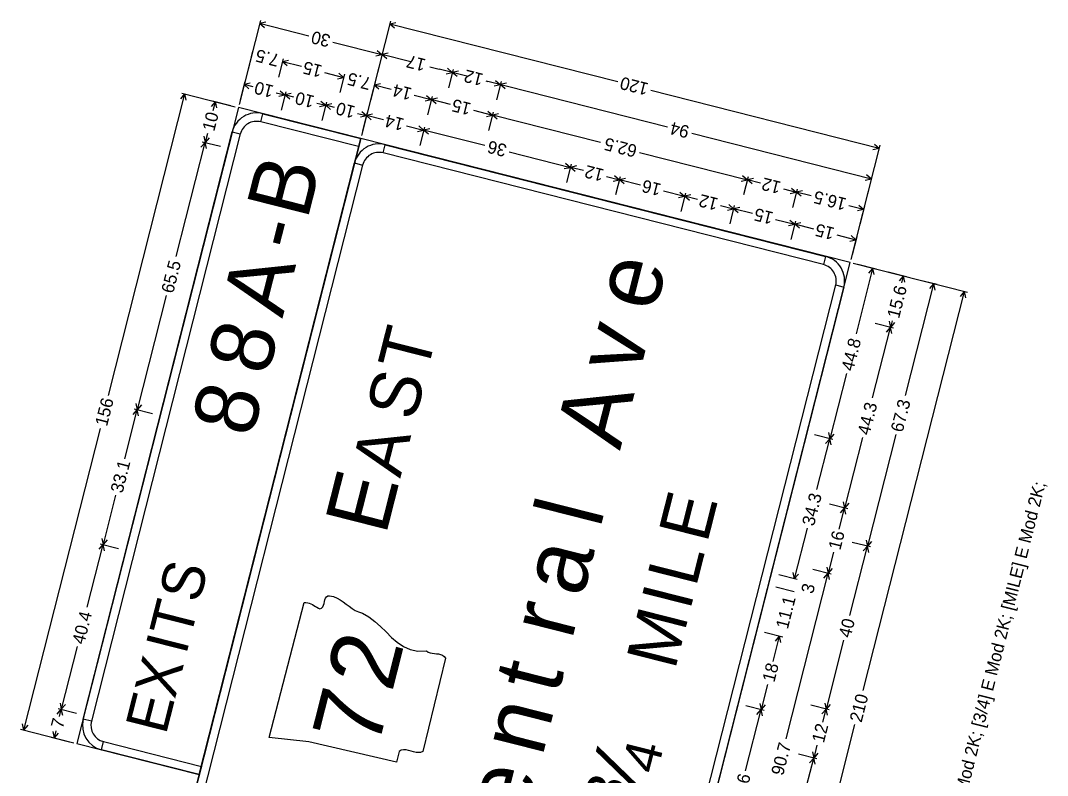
# Model space of a CAD drawing. Extents: x 670006 to 670131, y 737844 to 738002.
# Drawn here: x 670006.01 to 670044.77, y 737866.83 to 737895.33 of the extents above; entities that cross this region are included whole.
import ezdxf

# ---------------------------------------------------------------- set-up
doc = ezdxf.new("R2010")
doc.units = 0
doc.layers.add('R_SIGN', color=7, linetype='Continuous')

msp = doc.modelspace()

# ---------------------------------------------------------------- linework, layer by layer
at = {"layer": 'R_SIGN'}
for p, q in [((670015.059, 737895.329), (670014.256, 737892.162)), ((670015.262, 737895.264), (670015.03, 737895.213)), ((670016.884, 737894.743), (670015.03, 737895.213)), ((670015.21, 737895.058), (670015.03, 737895.213)), ((670019.97, 737895.309), (670018.874, 737890.99)), ((670020.173, 737895.244), (670019.941, 737895.194)), ((670028.558, 737893.008), (670019.941, 737895.194)), ((670020.12, 737895.038), (670019.941, 737895.194)), ((670017.794, 737894.512), (670019.648, 737894.042)), ((670014.767, 737894.177), (670014.592, 737893.486)), ((670019.678, 737894.157), (670018.874, 737890.99)), ((670019.416, 737893.991), (670019.648, 737894.042)), ((670019.469, 737894.197), (670019.648, 737894.042)), ((670019.678, 737894.157), (670019.502, 737893.466)), ((670019.881, 737894.093), (670019.648, 737894.042)), ((670020.736, 737893.766), (670019.648, 737894.042)), ((670019.828, 737893.887), (670019.648, 737894.042)), ((670015.922, 737893.884), (670015.746, 737893.193)), ((670016.125, 737893.82), (670015.893, 737893.769)), ((670016.611, 737893.587), (670015.893, 737893.769)), ((670016.072, 737893.614), (670015.893, 737893.769)), ((670017.483, 737893.366), (670018.202, 737893.183)), ((670018.022, 737893.339), (670018.202, 737893.183)), ((670018.231, 737893.298), (670018.056, 737892.607)), ((670018.231, 737893.298), (670018.056, 737892.607)), ((670021.451, 737893.585), (670021.804, 737893.495)), ((670022.906, 737893.216), (670021.804, 737893.495)), ((670022.072, 737893.318), (670022.304, 737893.368)), ((670022.124, 737893.524), (670022.304, 737893.368)), ((670022.333, 737893.484), (670022.158, 737892.793)), ((670022.536, 737893.419), (670022.304, 737893.368)), ((670022.484, 737893.213), (670022.304, 737893.368)), ((670014.475, 737893.025), (670014.3, 737892.334)), ((670014.678, 737892.961), (670014.446, 737892.91)), ((670014.781, 737892.825), (670014.446, 737892.91)), ((670014.626, 737892.755), (670014.446, 737892.91)), ((670017.97, 737893.132), (670018.202, 737893.183)), ((670019.386, 737893.006), (670019.21, 737892.315)), ((670019.386, 737893.006), (670019.21, 737892.315)), ((670019.588, 737892.941), (670019.356, 737892.89)), ((670020.001, 737892.727), (670019.356, 737892.89)), ((670019.536, 737892.735), (670019.356, 737892.89)), ((670023.569, 737893.048), (670023.651, 737893.027)), ((670030.432, 737891.307), (670023.651, 737893.027)), ((670023.881, 737892.859), (670024.113, 737892.91)), ((670023.933, 737893.065), (670024.113, 737892.91)), ((670024.142, 737893.025), (670023.967, 737892.334)), ((670024.345, 737892.96), (670024.113, 737892.91)), ((670024.293, 737892.754), (670024.113, 737892.91)), ((670009.324, 737881.172), (670012.211, 737892.558)), ((670012.056, 737892.378), (670012.211, 737892.558)), ((670012.096, 737892.587), (670014.112, 737892.076)), ((670012.262, 737892.325), (670012.211, 737892.558)), ((670015.65, 737892.605), (670015.985, 737892.52)), ((670015.753, 737892.469), (670015.985, 737892.52)), ((670015.805, 737892.675), (670015.985, 737892.52)), ((670016.014, 737892.635), (670015.839, 737891.944)), ((670016.217, 737892.57), (670015.985, 737892.52)), ((670016.32, 737892.435), (670015.985, 737892.52)), ((670016.165, 737892.364), (670015.985, 737892.52)), ((670020.868, 737892.507), (670021.512, 737892.344)), ((670021.332, 737892.499), (670021.512, 737892.344)), ((670029.797, 737892.694), (670038.415, 737890.508)), ((670013.208, 737892.086), (670013.363, 737892.265)), ((670013.248, 737892.295), (670013.939, 737892.119)), ((670013.278, 737891.93), (670013.363, 737892.265)), ((670013.414, 737892.033), (670013.363, 737892.265)), ((670017.19, 737892.214), (670017.525, 737892.129)), ((670017.293, 737892.078), (670017.525, 737892.129)), ((670017.345, 737892.284), (670017.525, 737892.129)), ((670017.554, 737892.244), (670017.379, 737891.553)), ((670017.554, 737892.244), (670017.379, 737891.553)), ((670017.757, 737892.18), (670017.525, 737892.129)), ((670017.86, 737892.044), (670017.525, 737892.129)), ((670017.705, 737891.974), (670017.525, 737892.129)), ((670021.28, 737892.293), (670021.512, 737892.344)), ((670021.541, 737892.459), (670021.366, 737891.768)), ((670021.744, 737892.395), (670021.512, 737892.344)), ((670022.23, 737892.162), (670021.512, 737892.344)), ((670021.692, 737892.188), (670021.512, 737892.344)), ((670014.227, 737892.046), (670008.136, 737868.03)), ((670018.845, 737890.875), (670014.227, 737892.046)), ((670015.072, 737891.504), (670015.15, 737891.812)), ((670018.729, 737891.824), (670019.064, 737891.739)), ((670018.832, 737891.688), (670019.064, 737891.739)), ((670018.884, 737891.894), (670019.064, 737891.739)), ((670019.093, 737891.854), (670018.918, 737891.163)), ((670019.093, 737891.854), (670018.918, 737891.163)), ((670019.296, 737891.789), (670019.064, 737891.739)), ((670019.708, 737891.575), (670019.064, 737891.739)), ((670019.244, 737891.583), (670019.064, 737891.739)), ((670023.102, 737891.94), (670023.821, 737891.758)), ((670023.589, 737891.707), (670023.821, 737891.758)), ((670023.641, 737891.913), (670023.821, 737891.758)), ((670023.85, 737891.873), (670023.675, 737891.182)), ((670024.053, 737891.809), (670023.821, 737891.758)), ((670027.896, 737890.725), (670023.821, 737891.758)), ((670024.001, 737891.603), (670023.821, 737891.758)), ((670020.575, 737891.355), (670021.22, 737891.192)), ((670021.04, 737891.347), (670021.22, 737891.192)), ((670012.922, 737890.958), (670012.973, 737890.726)), ((670013.058, 737891.061), (670012.973, 737890.726)), ((670013.992, 737891.123), (670014.3, 737891.045)), ((670020.987, 737891.141), (670021.22, 737891.192)), ((670021.249, 737891.307), (670021.074, 737890.616)), ((670021.452, 737891.243), (670021.22, 737891.192)), ((670023.532, 737890.606), (670021.22, 737891.192)), ((670021.399, 737891.037), (670021.22, 737891.192)), ((670031.342, 737891.076), (670038.122, 737889.357)), ((670018.845, 737890.875), (670010.88, 737859.469)), ((670011.88, 737886.416), (670012.973, 737890.726)), ((670012.754, 737866.859), (670018.845, 737890.875)), ((670012.817, 737890.546), (670012.973, 737890.726)), ((670012.857, 737890.755), (670013.548, 737890.58)), ((670012.857, 737890.755), (670013.548, 737890.58)), ((670013.128, 737890.906), (670012.973, 737890.726)), ((670013.023, 737890.494), (670012.973, 737890.726)), ((670037.319, 737886.19), (670018.845, 737890.875)), ((670019.691, 737890.333), (670019.769, 737890.641)), ((670038.444, 737890.623), (670037.348, 737886.305)), ((670038.235, 737890.663), (670038.415, 737890.508)), ((670024.449, 737890.373), (670026.762, 737889.786)), ((670029.368, 737890.351), (670033.443, 737889.318)), ((670038.182, 737890.457), (670038.415, 737890.508)), ((670018.611, 737889.951), (670018.919, 737889.873)), ((670026.53, 737889.736), (670026.762, 737889.786)), ((670026.582, 737889.942), (670026.762, 737889.786)), ((670026.791, 737889.902), (670026.616, 737889.211)), ((670026.994, 737889.837), (670026.762, 737889.786)), ((670027.252, 737889.662), (670026.762, 737889.786)), ((670026.942, 737889.631), (670026.762, 737889.786)), ((670028.119, 737889.442), (670028.609, 737889.318)), ((670028.429, 737889.473), (670028.609, 737889.318)), ((670028.638, 737889.433), (670028.463, 737888.742)), ((670033.263, 737889.473), (670033.443, 737889.318)), ((670033.472, 737889.433), (670033.297, 737888.742)), ((670037.943, 737889.512), (670038.122, 737889.357)), ((670038.152, 737889.472), (670037.976, 737888.781)), ((670028.377, 737889.267), (670028.609, 737889.318)), ((670028.841, 737889.369), (670028.609, 737889.318)), ((670029.403, 737889.117), (670028.609, 737889.318)), ((670028.789, 737889.163), (670028.609, 737889.318)), ((670033.211, 737889.267), (670033.443, 737889.318)), ((670033.675, 737889.369), (670033.443, 737889.318)), ((670033.933, 737889.193), (670033.443, 737889.318)), ((670033.623, 737889.162), (670033.443, 737889.318)), ((670035.11, 737889.004), (670035.29, 737888.849)), ((670037.89, 737889.306), (670038.122, 737889.357)), ((670030.279, 737888.894), (670031.072, 737888.693)), ((670030.84, 737888.642), (670031.072, 737888.693)), ((670030.893, 737888.848), (670031.072, 737888.693)), ((670031.102, 737888.808), (670030.926, 737888.117)), ((670031.305, 737888.744), (670031.072, 737888.693)), ((670031.563, 737888.569), (670031.072, 737888.693)), ((670031.252, 737888.538), (670031.072, 737888.693)), ((670034.8, 737888.974), (670035.29, 737888.849)), ((670035.058, 737888.798), (670035.29, 737888.849)), ((670035.319, 737888.964), (670035.144, 737888.273)), ((670035.319, 737888.964), (670035.144, 737888.273)), ((670035.522, 737888.9), (670035.29, 737888.849)), ((670035.847, 737888.708), (670035.29, 737888.849)), ((670035.47, 737888.694), (670035.29, 737888.849)), ((670032.43, 737888.349), (670032.92, 737888.225)), ((670032.688, 737888.174), (670032.92, 737888.225)), ((670032.74, 737888.38), (670032.92, 737888.225)), ((670032.949, 737888.34), (670032.774, 737887.649)), ((670033.152, 737888.275), (670032.92, 737888.225)), ((670033.638, 737888.042), (670032.92, 737888.225)), ((670033.1, 737888.069), (670032.92, 737888.225)), ((670037.274, 737888.346), (670037.83, 737888.205)), ((670037.651, 737888.36), (670037.83, 737888.205)), ((670037.86, 737888.32), (670037.684, 737887.629)), ((670037.598, 737888.154), (670037.83, 737888.205)), ((670034.51, 737887.821), (670035.229, 737887.639)), ((670034.997, 737887.588), (670035.229, 737887.639)), ((670035.049, 737887.794), (670035.229, 737887.639)), ((670035.258, 737887.754), (670035.083, 737887.063)), ((670035.258, 737887.754), (670035.083, 737887.063)), ((670035.461, 737887.69), (670035.229, 737887.639)), ((670035.948, 737887.457), (670035.229, 737887.639)), ((670035.409, 737887.484), (670035.229, 737887.639)), ((670036.82, 737887.236), (670037.538, 737887.053)), ((670037.358, 737887.209), (670037.538, 737887.053)), ((670037.568, 737887.168), (670037.392, 737886.478)), ((670037.306, 737887.003), (670037.538, 737887.053)), ((670036.396, 737886.424), (670036.317, 737886.116)), ((670029.354, 737854.784), (670037.319, 737886.19)), ((670041.753, 737885.065), (670037.434, 737886.16)), ((670037.556, 737883.498), (670038.183, 737885.971)), ((670038.298, 737885.941), (670037.607, 737886.117)), ((670038.028, 737885.791), (670038.183, 737885.971)), ((670038.234, 737885.738), (670038.183, 737885.971)), ((670039.45, 737885.649), (670038.759, 737885.825)), ((670039.179, 737885.499), (670039.335, 737885.678)), ((670039.271, 737885.427), (670039.335, 737885.678)), ((670039.385, 737885.446), (670039.335, 737885.678)), ((670040.601, 737885.357), (670039.91, 737885.532)), ((670036.777, 737885.344), (670037.085, 737885.266)), ((670039.417, 737881.17), (670040.486, 737885.386)), ((670040.331, 737885.207), (670040.486, 737885.386)), ((670040.537, 737885.154), (670040.486, 737885.386)), ((670011.506, 737884.944), (670010.413, 737880.635)), ((670037.818, 737870.035), (670041.638, 737885.094)), ((670041.483, 737884.915), (670041.638, 737885.094)), ((670041.689, 737884.862), (670041.638, 737885.094)), ((670038.793, 737883.977), (670038.844, 737883.745)), ((670038.908, 737883.996), (670038.844, 737883.745)), ((670038.168, 737881.078), (670038.844, 737883.745)), ((670038.959, 737883.716), (670038.268, 737883.891)), ((670038.959, 737883.716), (670038.268, 737883.891)), ((670038.689, 737883.565), (670038.844, 737883.745)), ((670038.999, 737883.925), (670038.844, 737883.745)), ((670038.895, 737883.513), (670038.844, 737883.745)), ((670037.178, 737882.009), (670036.551, 737879.537)), ((670010.362, 737880.867), (670010.413, 737880.635)), ((670009.942, 737878.777), (670010.413, 737880.635)), ((670010.258, 737880.455), (670010.413, 737880.635)), ((670010.298, 737880.664), (670010.989, 737880.488)), ((670010.568, 737880.814), (670010.413, 737880.635)), ((670010.464, 737880.402), (670010.413, 737880.635)), ((670009.008, 737879.927), (670006.12, 737868.541)), ((670036.5, 737879.769), (670036.551, 737879.537)), ((670036.706, 737879.717), (670036.551, 737879.537)), ((670039.044, 737879.698), (670037.974, 737875.482)), ((670036.666, 737879.508), (670035.975, 737879.683)), ((670036.666, 737879.508), (670035.975, 737879.683)), ((670036.067, 737877.629), (670036.551, 737879.537)), ((670036.396, 737879.357), (670036.551, 737879.537)), ((670036.602, 737879.305), (670036.551, 737879.537)), ((670037.79, 737879.589), (670037.114, 737876.922)), ((670009.594, 737877.404), (670009.123, 737875.546)), ((670037.229, 737876.893), (670036.538, 737877.068)), ((670037.063, 737877.154), (670037.114, 737876.922)), ((670037.269, 737877.102), (670037.114, 737876.922)), ((670036.913, 737876.128), (670037.114, 737876.922)), ((670036.958, 737876.742), (670037.114, 737876.922)), ((670037.165, 737876.69), (670037.114, 737876.922)), ((670035.695, 737876.161), (670035.211, 737874.253)), ((670008.522, 737873.179), (670009.123, 737875.546)), ((670008.968, 737875.367), (670009.123, 737875.546)), ((670009.008, 737875.576), (670009.699, 737875.4)), ((670009.072, 737875.779), (670009.123, 737875.546)), ((670009.278, 737875.726), (670009.123, 737875.546)), ((670009.173, 737875.314), (670009.123, 737875.546)), ((670037.312, 737872.872), (670037.974, 737875.482)), ((670038.089, 737875.453), (670037.398, 737875.628)), ((670038.089, 737875.453), (670037.398, 737875.628)), ((670037.819, 737875.302), (670037.974, 737875.482)), ((670037.923, 737875.714), (670037.974, 737875.482)), ((670038.129, 737875.662), (670037.974, 737875.482)), ((670038.025, 737875.25), (670037.974, 737875.482)), ((670036.69, 737875.252), (670036.489, 737874.459)), ((670036.438, 737874.691), (670036.489, 737874.459)), ((670035.326, 737874.224), (670034.635, 737874.399)), ((670034.904, 737868.209), (670036.489, 737874.459)), ((670035.16, 737874.486), (670035.211, 737874.253)), ((670035.366, 737874.433), (670035.211, 737874.253)), ((670036.604, 737874.429), (670035.913, 737874.605)), ((670036.334, 737874.279), (670036.489, 737874.459)), ((670036.644, 737874.638), (670036.489, 737874.459)), ((670036.54, 737874.226), (670036.489, 737874.459)), ((670035.209, 737873.762), (670034.518, 737873.938)), ((670017.492, 737873.463), (670017.515, 737873.523)), ((670017.515, 737873.523), (670017.549, 737873.572)), ((670017.549, 737873.572), (670017.599, 737873.604)), ((670017.599, 737873.604), (670017.671, 737873.614)), ((670017.671, 737873.614), (670017.819, 737873.579)), ((670017.819, 737873.579), (670017.953, 737873.525)), ((670017.953, 737873.525), (670018.075, 737873.457)), ((670015.388, 737868.263), (670016.714, 737873.358)), ((670016.714, 737873.358), (670016.78, 737873.357)), ((670016.714, 737873.358), (670016.714, 737873.358)), ((670016.78, 737873.357), (670016.845, 737873.347)), ((670016.845, 737873.347), (670016.906, 737873.329)), ((670016.906, 737873.329), (670016.966, 737873.305)), ((670016.966, 737873.305), (670017.025, 737873.277)), ((670017.025, 737873.277), (670017.082, 737873.246)), ((670017.082, 737873.246), (670017.139, 737873.212)), ((670017.139, 737873.212), (670017.194, 737873.178)), ((670017.194, 737873.178), (670017.249, 737873.146)), ((670017.249, 737873.146), (670017.305, 737873.114)), ((670017.305, 737873.114), (670017.369, 737873.147)), ((670017.369, 737873.147), (670017.413, 737873.196)), ((670017.413, 737873.196), (670017.442, 737873.256)), ((670017.442, 737873.256), (670017.461, 737873.325)), ((670017.461, 737873.325), (670017.476, 737873.395)), ((670017.476, 737873.395), (670017.492, 737873.463)), ((670018.075, 737873.457), (670018.189, 737873.379)), ((670018.189, 737873.379), (670018.3, 737873.296)), ((670018.3, 737873.296), (670018.409, 737873.213)), ((670018.409, 737873.213), (670018.522, 737873.132)), ((670018.522, 737873.132), (670018.641, 737873.061)), ((670018.641, 737873.061), (670018.769, 737873)), ((670018.769, 737873), (670018.91, 737872.957)), ((670018.91, 737872.957), (670019.159, 737872.817)), ((670019.159, 737872.817), (670019.385, 737872.643)), ((670019.385, 737872.643), (670019.597, 737872.449)), ((670019.597, 737872.449), (670019.804, 737872.244)), ((670019.804, 737872.244), (670020.01, 737872.042)), ((670020.01, 737872.042), (670020.226, 737871.857)), ((670034.776, 737872.054), (670034.085, 737872.229)), ((670034.42, 737871.133), (670034.661, 737872.083)), ((670034.505, 737871.903), (670034.661, 737872.083)), ((670034.711, 737871.851), (670034.661, 737872.083)), ((670037.076, 737871.94), (670036.414, 737869.33)), ((670008.146, 737871.694), (670007.545, 737869.327)), ((670020.226, 737871.857), (670020.458, 737871.702)), ((670020.458, 737871.702), (670020.714, 737871.587)), ((670020.714, 737871.587), (670021.001, 737871.526)), ((670021.001, 737871.526), (670021.326, 737871.532)), ((670022.045, 737871.256), (670021.185, 737867.729)), ((670021.326, 737871.532), (670021.395, 737871.488)), ((670021.395, 737871.488), (670021.47, 737871.46)), ((670021.47, 737871.46), (670021.548, 737871.442)), ((670021.548, 737871.442), (670021.629, 737871.432)), ((670021.629, 737871.432), (670021.709, 737871.423)), ((670021.709, 737871.423), (670021.788, 737871.413)), ((670021.788, 737871.413), (670021.863, 737871.396)), ((670021.863, 737871.396), (670021.931, 737871.367)), ((670021.931, 737871.367), (670021.993, 737871.323)), ((670021.993, 737871.323), (670022.045, 737871.256)), ((670034.199, 737870.261), (670033.958, 737869.312)), ((670007.39, 737869.147), (670007.545, 737869.327)), ((670007.43, 737869.356), (670008.121, 737869.181)), ((670007.477, 737869.059), (670007.545, 737869.327)), ((670007.495, 737869.559), (670007.545, 737869.327)), ((670007.701, 737869.507), (670007.545, 737869.327)), ((670007.596, 737869.095), (670007.545, 737869.327)), ((670033.371, 737866.999), (670033.958, 737869.312)), ((670034.073, 737869.282), (670033.382, 737869.458)), ((670033.803, 737869.132), (670033.958, 737869.312)), ((670033.907, 737869.544), (670033.958, 737869.312)), ((670034.113, 737869.491), (670033.958, 737869.312)), ((670034.009, 737869.08), (670033.958, 737869.312)), ((670036.529, 737869.301), (670035.838, 737869.476)), ((670036.259, 737869.15), (670036.414, 737869.33)), ((670036.29, 737868.84), (670036.414, 737869.33)), ((670036.363, 737869.562), (670036.414, 737869.33)), ((670036.569, 737869.51), (670036.414, 737869.33)), ((670036.465, 737869.098), (670036.414, 737869.33)), ((670008.678, 737868.876), (670008.37, 737868.954)), ((670006.005, 737868.571), (670008.021, 737868.059)), ((670006.07, 737868.773), (670006.12, 737868.541)), ((670006.276, 737868.721), (670006.12, 737868.541)), ((670007.221, 737868.481), (670007.272, 737868.249)), ((670007.34, 737868.517), (670007.272, 737868.249)), ((670037.492, 737868.748), (670033.673, 737853.688)), ((670007.157, 737868.278), (670007.848, 737868.103)), ((670007.427, 737868.429), (670007.272, 737868.249)), ((670009.059, 737867.796), (670009.137, 737868.104)), ((670016.891, 737868.101), (670015.388, 737868.263)), ((670020.191, 737867.327), (670016.891, 737868.101)), ((670008.136, 737868.03), (670012.754, 737866.859)), ((670020.295, 737867.737), (670020.191, 737867.327)), ((670020.377, 737867.78), (670020.295, 737867.737)), ((670020.464, 737867.795), (670020.377, 737867.78)), ((670020.556, 737867.792), (670020.464, 737867.795)), ((670020.652, 737867.774), (670020.556, 737867.792)), ((670020.747, 737867.749), (670020.652, 737867.774)), ((670020.843, 737867.723), (670020.747, 737867.749)), ((670020.935, 737867.7), (670020.843, 737867.723)), ((670021.024, 737867.69), (670020.935, 737867.7)), ((670021.108, 737867.698), (670021.024, 737867.69)), ((670021.185, 737867.729), (670021.108, 737867.698)), ((670035.895, 737867.715), (670035.945, 737867.483)), ((670036.07, 737867.973), (670035.945, 737867.483)), ((670036.061, 737867.454), (670035.37, 737867.629)), ((670035.676, 737866.42), (670035.945, 737867.483)), ((670035.79, 737867.303), (670035.945, 737867.483)), ((670036.101, 737867.663), (670035.945, 737867.483)), ((670035.996, 737867.251), (670035.945, 737867.483)), ((670012.754, 737866.859), (670012.754, 737866.859))]:
    msp.add_line(p, q, dxfattribs=at)
for points in [[(670018.767, 737890.567), (670015.072, 737891.504), (670015.15, 737891.812), (670018.845, 737890.875), (670018.767, 737890.567)], [(670014.3, 737891.045), (670008.678, 737868.876), (670008.37, 737868.954), (670013.992, 737891.123), (670014.3, 737891.045)], [(670036.317, 737886.116), (670019.691, 737890.333), (670019.769, 737890.641), (670036.396, 737886.424), (670036.317, 737886.116)], [(670018.919, 737889.873), (670011.422, 737860.315), (670011.114, 737860.393), (670018.611, 737889.951), (670018.919, 737889.873)], [(670029.28, 737855.786), (670036.777, 737885.344), (670037.085, 737885.266), (670029.588, 737855.707), (670029.28, 737855.786)], [(670009.137, 737868.104), (670012.832, 737867.167), (670012.754, 737866.859), (670009.059, 737867.796), (670009.137, 737868.104)]]:
    msp.add_lwpolyline(points, close=True, dxfattribs=at)
for centre, radius, start, end in [((670014.916, 737890.888), 0.953, 75.7686, 165.7688), ((670014.916, 737890.888), 0.635, 75.7686, 165.7688), ((670019.535, 737889.717), 0.953, 75.7686, 165.7688), ((670019.535, 737889.717), 0.635, 75.7686, 165.7688), ((670036.161, 737885.5), 0.953, 345.7686, 75.7688), ((670036.161, 737885.5), 0.635, 345.7686, 75.7688), ((670009.294, 737868.72), 0.953, 165.7688, 255.7684), ((670009.294, 737868.72), 0.635, 165.7688, 255.7684)]:
    msp.add_arc(centre, radius, start, end, dxfattribs=at)

# ---------------------------------------------------------------- texts
for s, height, rotation, p in [('30', 0.4752, 165.7688, (670017.738, 737894.772)), ('7.5', 0.4752, 165.7688, (670015.808, 737894.036)), ('15', 0.4752, 165.7688, (670017.426, 737893.625)), ('17', 0.4752, 165.7688, (670021.335, 737893.859)), ('7.5', 0.4752, 165.7688, (670019.272, 737893.157)), ('12', 0.4752, 165.7688, (670023.507, 737893.309)), ('10', 0.4752, 165.7688, (670015.594, 737892.864)), ('14', 0.4752, 165.7688, (670020.811, 737892.767)), ('120', 0.4752, 165.7688, (670029.74, 737892.953)), ('10', 0.4752, 165.7688, (670017.133, 737892.474)), ('10', 0.4752, 165.7688, (670018.673, 737892.083)), ('15', 0.4752, 165.7688, (670023.046, 737892.2)), ('10', 0.4752, 75.7686, (670013.317, 737891.118)), ('14', 0.4752, 165.7688, (670020.519, 737891.615)), ('94', 0.4752, 165.7688, (670031.285, 737891.336)), ('36', 0.4752, 165.7688, (670024.393, 737890.632)), ('62.5', 0.4752, 165.7688, (670029.311, 737890.611)), ('B', 2.382, 75.7686, (670016.826, 737887.758)), ('12', 0.4752, 165.7688, (670028.062, 737889.702)), ('12', 0.4752, 165.7688, (670034.743, 737889.233)), ('16', 0.4752, 165.7688, (670030.222, 737889.154)), ('12', 0.4752, 165.7688, (670032.373, 737888.608)), ('16.5', 0.4752, 165.7688, (670037.217, 737888.606)), ('15', 0.4752, 165.7688, (670034.454, 737888.081)), ('-', 2.382, 75.7686, (670016.521, 737886.557)), ('15', 0.4752, 165.7688, (670036.763, 737887.495)), ('e', 2.541, 75.7686, (670029.951, 737884.27)), ('65.5', 0.4752, 75.7686, (670011.766, 737885.001)), ('A', 2.382, 75.7686, (670015.889, 737884.063)), ('15.6', 0.4752, 75.7686, (670039.167, 737884.053)), ('v', 2.541, 75.7686, (670029.345, 737881.881)), ('8', 2.382, 75.7686, (670015.332, 737881.869)), ('T', 1.906, 75.7686, (670021.331, 737881.942)), ('44.8', 0.4752, 75.7686, (670037.438, 737882.066)), ('S', 1.906, 75.7686, (670020.882, 737880.169)), ('8', 2.382, 75.7686, (670014.741, 737879.537)), ('A', 2.541, 75.7686, (670028.632, 737879.073)), ('156', 0.4752, 75.7686, (670009.268, 737879.983)), ('44.3', 0.4752, 75.7686, (670038.05, 737879.645)), ('67.3', 0.4752, 75.7686, (670039.303, 737879.755)), ('A', 1.906, 75.7686, (670020.338, 737878.026)), ('33.1', 0.4752, 75.7686, (670009.853, 737877.46)), ('E', 2.382, 75.7686, (670019.788, 737875.855)), ('[E] E Mod 2K; [AST] E Mod 2K; [E Central Ave] E Mod 2K; [3/4] E Mod 2K; [MILE] E Mod 2K; ', 0.47522, 75.7686, (670038.279, 737852.52)), ('E', 1.906, 75.7686, (670031.92, 737875.562)), ('34.3', 0.4752, 75.7686, (670035.955, 737876.218)), ('l', 2.541, 75.7686, (670027.883, 737876.117)), ('16', 0.4752, 75.7686, (670036.95, 737875.309)), ('a', 2.541, 75.7686, (670027.221, 737873.506)), ('L', 1.906, 75.7686, (670031.499, 737873.9)), ('S', 1.588, 75.7686, (670012.749, 737873.3)), ('I', 1.906, 75.7686, (670031.274, 737873.013)), ('3', 0.475, 75.7686, (670035.919, 737873.661)), ('T', 1.588, 75.7686, (670012.402, 737871.929)), ('11.1', 0.4752, 75.7686, (670034.968, 737872.328)), ('r', 2.541, 75.7686, (670026.815, 737871.905)), ('40.4', 0.4752, 75.7686, (670008.405, 737871.751)), ('M', 1.906, 75.7686, (670030.707, 737870.778)), ('40', 0.4752, 75.7686, (670037.335, 737871.997)), ('I', 1.588, 75.7686, (670012.253, 737871.344)), ('2', 2.573, 75.7686, (670020.023, 737869.929)), ('X', 1.588, 75.7686, (670011.832, 737869.682)), ('t', 2.541, 75.7686, (670026.29, 737869.836)), ('18', 0.4752, 75.7686, (670034.458, 737870.318)), ('7', 2.573, 75.7686, (670019.485, 737867.809)), ('E', 1.588, 75.7686, (670011.488, 737868.327)), ('210', 0.4752, 75.7686, (670037.752, 737868.805)), ('n', 2.541, 75.7686, (670025.696, 737867.496)), ('7', 0.475, 75.7686, (670007.6, 737868.574)), ('12', 0.4752, 75.7686, (670036.329, 737868.03)), ('90.7', 0.4752, 75.7686, (670034.791, 737866.798)), ('¾', 2.382, 75.7686, (670029.557, 737865.274)), ('e', 2.541, 75.7686, (670025.09, 737865.106)), ('36', 0.4752, 75.7686, (670033.398, 737866.138))]:
    msp.add_text(s, height=height, rotation=rotation, dxfattribs=at).set_placement(p)

doc.saveas('drawing.dxf')
